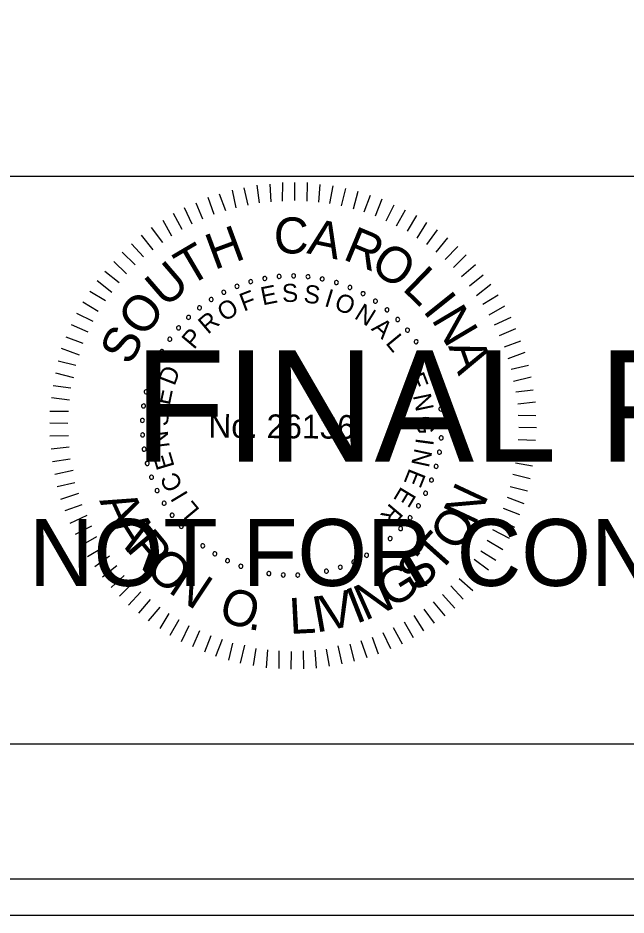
# Model space of a CAD drawing. Extents: x 967 to 1326, y 964 to 1744.
# Drawn here: x 1170.56 to 1189.3, y 963.72 to 991.36 of the extents above; entities that cross this region are included whole.
import ezdxf

# ---------------------------------------------------------------- set-up
doc = ezdxf.new("R2010")
doc.units = 0
for name, color, linetype in [('RD_PD_PaveShd', 7, 'Continuous'), ('RD_XS_Base', 7, 'Continuous'), ('RD_XS_CurbBase', 7, 'Continuous'), ('RD_XS_TieSlope', 7, 'Continuous'), ('RD_XS_TX_TOC', 7, 'Continuous')]:
    doc.layers.add(name, color=color, linetype=linetype)

msp = doc.modelspace()

# ---------------------------------------------------------------- linework, layer by layer
at = {"layer": 'RD_PD_PaveShd'}
for p, q in [((996.114, 986.486), (1323.886, 986.486)), ((1323.886, 968.983), (996.114, 968.983))]:
    msp.add_line(p, q, dxfattribs=at)
at = {"layer": 'RD_XS_CurbBase'}
msp.add_lwpolyline([(967.409, 963.72), (1326.285, 963.72), (1326.285, 1183.72), (967.409, 1183.72)], close=True, dxfattribs=at)
at = {"layer": 'RD_XS_TieSlope'}
for p, q in [((1178.01, 985.663), (1177.93, 986.209)), ((1178.364, 985.699), (1178.33, 986.244)), ((1178.717, 985.719), (1178.722, 986.295)), ((1179.093, 985.739), (1179.098, 986.292)), ((1179.469, 985.713), (1179.489, 986.288)), ((1179.829, 985.687), (1179.872, 986.231)), ((1180.174, 985.646), (1180.271, 986.19)), ((1176.964, 985.419), (1176.769, 985.935)), ((1177.287, 985.508), (1177.169, 986.054)), ((1177.657, 985.597), (1177.53, 986.128)), ((1180.535, 985.573), (1180.662, 986.102)), ((1180.902, 985.478), (1181.045, 986.022)), ((1176.264, 985.156), (1176.053, 985.657)), ((1176.61, 985.306), (1176.423, 985.83)), ((1181.231, 985.384), (1181.428, 985.896)), ((1181.584, 985.265), (1181.78, 985.786)), ((1175.933, 985.005), (1175.699, 985.506)), ((1181.905, 985.109), (1182.154, 985.606)), ((1182.226, 984.953), (1182.506, 985.45)), ((1175.308, 984.634), (1175.036, 985.12)), ((1175.624, 984.846), (1175.352, 985.332)), ((1182.562, 984.789), (1182.85, 985.27)), ((1175.03, 984.445), (1174.681, 984.9)), ((1182.86, 984.572), (1183.163, 985.053)), ((1183.158, 984.378), (1183.484, 984.828)), ((1174.729, 984.217), (1174.372, 984.665)), ((1183.447, 984.145), (1183.811, 984.587)), ((1174.435, 983.997), (1174.062, 984.399)), ((1183.729, 983.92), (1184.116, 984.316)), ((1174.172, 983.753), (1173.776, 984.148)), ((1183.98, 983.672), (1184.368, 984.061)), ((1173.909, 983.479), (1173.52, 983.858)), ((1184.232, 983.394), (1184.657, 983.767)), ((1173.684, 983.197), (1173.242, 983.546)), ((1184.475, 983.108), (1184.892, 983.45)), ((1173.451, 982.9), (1173.009, 983.256)), ((1184.687, 982.807), (1185.128, 983.156)), ((1173.257, 982.64), (1172.776, 982.936)), ((1173.039, 982.312), (1172.559, 982.6)), ((1184.885, 982.544), (1185.355, 982.832)), ((1185.081, 982.213), (1185.56, 982.493)), ((1172.883, 982.006), (1172.379, 982.256)), ((1185.24, 981.904), (1185.756, 982.145)), ((1172.727, 981.677), (1172.215, 981.904)), ((1185.399, 981.573), (1185.907, 981.791)), ((1172.571, 981.333), (1172.051, 981.53)), ((1185.549, 981.226), (1186.057, 981.414)), ((1172.461, 980.974), (1171.91, 981.178)), ((1185.669, 980.865), (1186.185, 981.06)), ((1172.351, 980.652), (1171.807, 980.787)), ((1185.759, 980.541), (1186.297, 980.667)), ((1172.286, 980.276), (1171.727, 980.419)), ((1185.832, 980.165), (1186.371, 980.298)), ((1172.191, 979.955), (1171.647, 980.029)), ((1185.906, 979.842), (1186.436, 979.906)), ((1172.15, 979.587), (1171.598, 979.653)), ((1185.964, 979.473), (1186.51, 979.53)), ((1172.124, 979.234), (1171.548, 979.239)), ((1185.977, 979.12), (1186.514, 979.115)), ((1172.105, 978.866), (1171.545, 978.871)), ((1185.997, 978.751), (1186.542, 978.747)), ((1172.118, 978.482), (1171.542, 978.471)), ((1185.971, 978.368), (1186.508, 978.348)), ((1172.138, 978.136), (1171.585, 978.072)), ((1185.952, 978.022), (1186.497, 977.949)), ((1172.173, 977.768), (1171.627, 977.688)), ((1185.888, 977.655), (1186.417, 977.566)), ((1172.262, 977.414), (1171.701, 977.296)), ((1185.808, 977.302), (1186.345, 977.175)), ((1172.321, 977.037), (1171.774, 976.911)), ((1185.729, 976.926), (1186.265, 976.792)), ((1172.425, 976.707), (1171.871, 976.519)), ((1185.634, 976.597), (1186.146, 976.401)), ((1172.53, 976.36), (1172.007, 976.173)), ((1185.508, 976.253), (1186.013, 976.057)), ((1172.681, 976.029), (1172.165, 975.788)), ((1172.831, 975.705), (1172.323, 975.441)), ((1185.352, 975.924), (1185.857, 975.675)), ((1185.188, 975.603), (1185.7, 975.33)), ((1172.982, 975.374), (1172.497, 975.094)), ((1185.024, 975.274), (1185.498, 974.987)), ((1173.194, 975.042), (1172.709, 974.762)), ((1184.822, 974.946), (1185.288, 974.658)), ((1173.384, 974.78), (1172.936, 974.453)), ((1184.62, 974.687), (1185.055, 974.353)), ((1173.612, 974.478), (1173.164, 974.129)), ((1184.403, 974.389), (1184.814, 974.033)), ((1173.832, 974.177), (1173.437, 973.812)), ((1184.155, 974.092), (1184.574, 973.72)), ((1174.091, 973.945), (1173.689, 973.541)), ((1183.899, 973.864), (1184.28, 973.454)), ((1174.35, 973.674), (1173.97, 973.263)), ((1183.644, 973.597), (1184.024, 973.18)), ((1174.64, 973.442), (1174.275, 973.022)), ((1174.937, 973.209), (1174.58, 972.782)), ((1183.358, 973.37), (1183.715, 972.944)), ((1175.212, 973.014), (1174.932, 972.549)), ((1182.764, 972.952), (1183.059, 972.482)), ((1183.065, 973.141), (1183.384, 972.709)), ((1175.525, 972.812), (1175.245, 972.331)), ((1182.463, 972.755), (1182.743, 972.269)), ((1175.83, 972.633), (1175.588, 972.136)), ((1176.159, 972.477), (1175.94, 971.98)), ((1181.8, 972.431), (1182.041, 971.93)), ((1182.124, 972.581), (1182.396, 972.08)), ((1176.503, 972.321), (1176.307, 971.816)), ((1176.855, 972.211), (1176.651, 971.69)), ((1177.177, 972.1), (1177.05, 971.572)), ((1181.122, 972.175), (1181.31, 971.652)), ((1181.476, 972.28), (1181.664, 971.771)), ((1177.545, 972.036), (1177.409, 971.484)), ((1177.897, 971.933), (1177.808, 971.412)), ((1178.25, 971.892), (1178.207, 971.34)), ((1178.603, 971.866), (1178.598, 971.313)), ((1178.978, 971.84), (1178.974, 971.295)), ((1179.355, 971.86), (1179.365, 971.307)), ((1179.715, 971.88), (1179.749, 971.327)), ((1180.061, 971.915), (1180.149, 971.393)), ((1180.423, 972.012), (1180.541, 971.458)), ((1180.791, 972.07), (1180.926, 971.54))]:
    msp.add_line(p, q, dxfattribs=at)
for centre, start, end in [((1178.609, 983.397), 5.0653, 185.0653), ((1179.055, 983.414), 359.5268, 179.5268), ((1179.5, 983.388), 353.9884, 173.9884), ((1177.312, 983.091), 21.6807, 201.6807), ((1177.734, 983.235), 16.1422, 196.1422), ((1177.734, 983.235), 196.1422, 16.1422), ((1178.168, 983.337), 10.6038, 190.6038), ((1178.168, 983.337), 190.6038, 10.6038), ((1178.609, 983.397), 185.0653, 5.0653), ((1179.055, 983.414), 179.5268, 359.5268), ((1179.5, 983.388), 173.9884, 353.9884), ((1179.94, 983.319), 168.4499, 348.4499), ((1179.94, 983.319), 348.4499, 168.4499), ((1180.372, 983.208), 162.9114, 342.9114), ((1180.372, 983.208), 342.9114, 162.9114), ((1176.906, 982.908), 27.2191, 207.2191), ((1176.906, 982.908), 207.2191, 27.2191), ((1177.312, 983.091), 201.6807, 21.6807), ((1180.79, 983.056), 157.373, 337.373), ((1180.79, 983.056), 337.373, 157.373), ((1181.193, 982.864), 151.8345, 331.8345), ((1181.193, 982.864), 331.8345, 151.8345), ((1176.52, 982.686), 32.7576, 212.7576), ((1176.52, 982.686), 212.7576, 32.7576), ((1181.574, 982.634), 146.2961, 326.2961), ((1181.574, 982.634), 326.2961, 146.2961), ((1176.156, 982.428), 38.2961, 218.2961), ((1176.156, 982.428), 218.2961, 38.2961), ((1181.932, 982.368), 140.7576, 320.7576), ((1181.932, 982.368), 320.7576, 140.7576), ((1175.82, 982.135), 43.8345, 223.8345), ((1175.82, 982.135), 223.8345, 43.8345), ((1182.263, 982.069), 135.2191, 315.2191), ((1182.263, 982.069), 315.2191, 135.2191), ((1175.513, 981.812), 49.373, 229.373), ((1175.513, 981.812), 229.373, 49.373), ((1182.563, 981.74), 129.6807, 309.6807), ((1182.563, 981.74), 309.6807, 129.6807), ((1175.239, 981.461), 54.9114, 234.9114), ((1175.239, 981.461), 234.9114, 54.9114), ((1182.83, 981.383), 124.1422, 304.1422), ((1182.83, 981.383), 304.1422, 124.1422), ((1175, 981.085), 60.4499, 240.4499), ((1175, 981.085), 240.4499, 60.4499), ((1183.061, 981.002), 118.6038, 298.6038), ((1183.061, 981.002), 298.6038, 118.6038), ((1174.798, 980.687), 65.9884, 245.9884), ((1174.798, 980.687), 245.9884, 65.9884), ((1183.255, 980.601), 293.0653, 113.0653), ((1183.255, 980.601), 113.0653, 293.0653), ((1174.636, 980.272), 71.5268, 251.5268), ((1174.636, 980.272), 251.5268, 71.5268), ((1183.408, 980.182), 107.5268, 287.5268), ((1183.408, 980.182), 287.5268, 107.5268), ((1174.514, 979.843), 77.0653, 257.0653), ((1174.514, 979.843), 257.0653, 77.0653), ((1183.521, 979.751), 101.9884, 281.9884), ((1183.521, 979.751), 281.9884, 101.9884), ((1174.435, 979.405), 82.6038, 262.6038), ((1174.435, 979.405), 262.6038, 82.6038), ((1183.592, 979.311), 96.4499, 276.4499), ((1183.592, 979.311), 276.4499, 96.4499), ((1174.398, 978.961), 88.1422, 268.1422), ((1174.398, 978.961), 268.1422, 88.1422), ((1183.619, 978.866), 90.9114, 270.9114), ((1183.619, 978.866), 270.9114, 90.9114), ((1174.404, 978.515), 93.6807, 273.6807), ((1174.404, 978.515), 273.6807, 93.6807), ((1183.604, 978.421), 85.373, 265.373), ((1183.604, 978.421), 265.373, 85.373), ((1174.453, 978.072), 99.2191, 279.2191), ((1174.453, 978.072), 279.2191, 99.2191), ((1183.546, 977.979), 79.8345, 259.8345), ((1183.546, 977.979), 259.8345, 79.8345), ((1174.545, 977.636), 104.7576, 284.7576), ((1174.545, 977.636), 284.7576, 104.7576), ((1183.445, 977.545), 74.2961, 254.2961), ((1183.445, 977.545), 254.2961, 74.2961), ((1174.678, 977.211), 110.2961, 290.2961), ((1174.678, 977.211), 290.2961, 110.2961), ((1183.303, 977.122), 68.7576, 248.7576), ((1183.303, 977.122), 248.7576, 68.7576), ((1174.852, 976.8), 115.8345, 295.8345), ((1174.852, 976.8), 295.8345, 115.8345), ((1183.121, 976.716), 63.2191, 243.2191), ((1183.121, 976.716), 243.2191, 63.2191), ((1175.065, 976.409), 121.373, 301.373), ((1175.065, 976.409), 301.373, 121.373), ((1182.9, 976.328), 57.6807, 237.6807), ((1182.9, 976.328), 237.6807, 57.6807), ((1175.314, 976.039), 126.9114, 306.9114), ((1175.314, 976.039), 306.9114, 126.9114), ((1182.643, 975.964), 52.1422, 232.1422), ((1182.643, 975.964), 232.1422, 52.1422), ((1175.598, 975.696), 132.4499, 312.4499), ((1175.598, 975.696), 312.4499, 132.4499), ((1182.353, 975.627), 46.6038, 226.6038), ((1175.914, 975.381), 137.9884, 317.9884), ((1175.914, 975.381), 317.9884, 137.9884), ((1182.353, 975.627), 226.6038, 46.6038), ((1176.258, 975.099), 143.5268, 323.5268), ((1176.258, 975.099), 323.5268, 143.5268), ((1182.03, 975.319), 41.0653, 221.0653), ((1182.03, 975.319), 221.0653, 41.0653), ((1176.629, 974.851), 149.0653, 329.0653), ((1176.629, 974.851), 329.0653, 149.0653), ((1181.305, 974.803), 29.9884, 209.9884), ((1181.68, 975.043), 35.5268, 215.5268), ((1181.68, 975.043), 215.5268, 35.5268), ((1177.021, 974.639), 154.6038, 334.6038), ((1177.021, 974.639), 334.6038, 154.6038), ((1180.908, 974.6), 24.4499, 204.4499), ((1180.908, 974.6), 204.4499, 24.4499), ((1181.305, 974.803), 209.9884, 29.9884), ((1177.432, 974.467), 160.1422, 340.1422), ((1177.432, 974.467), 340.1422, 160.1422), ((1177.858, 974.335), 165.6807, 345.6807), ((1177.858, 974.335), 345.6807, 165.6807), ((1178.294, 974.245), 351.2191, 171.2191), ((1180.065, 974.313), 13.373, 193.373), ((1180.065, 974.313), 193.373, 13.373), ((1180.494, 974.436), 18.9114, 198.9114), ((1180.494, 974.436), 198.9114, 18.9114), ((1178.294, 974.245), 171.2191, 351.2191), ((1178.737, 974.198), 356.7576, 176.7576), ((1178.737, 974.198), 176.7576, 356.7576), ((1179.183, 974.193), 2.2961, 182.2961), ((1179.183, 974.193), 182.2961, 2.2961), ((1179.627, 974.232), 7.8345, 187.8345), ((1179.627, 974.232), 187.8345, 7.8345)]:
    msp.add_arc(centre, 0.0627, start, end, dxfattribs=at)
at = {"layer": 'RD_XS_TX_TOC'}
for points in [[(967.409, 963.72), (1326.285, 963.72), (1326.285, 1183.72), (967.409, 1183.72)], [(988.525, 964.84), (1326.285, 964.84), (1326.285, 1182.6), (988.525, 1182.6)]]:
    msp.add_lwpolyline(points, close=True, dxfattribs=at)

# ---------------------------------------------------------------- texts
at = {"layer": 'RD_XS_Base'}
for s, height, p in [('FINAL PLANS', 3.4375, (1174.145, 977.685)), ('NOT FOR CONSTRUCTION', 2.0625, (1170.901, 973.86))]:
    msp.add_text(s, height=height, dxfattribs=at).set_placement(p)
at = {"layer": 'RD_XS_TieSlope'}
for s, height, rotation, p in [('C', 1.11, 359.5482, (1178.442, 984.108)), ('A', 1.11, 348.1981, (1179.439, 984.115)), ('H', 1.11, 20.3637, (1176.614, 983.587)), ('R', 1.11, 337.4344, (1180.541, 983.937)), ('T', 1.11, 30.4992, (1175.828, 983.072)), ('O', 1.108, 326.5869, (1181.366, 983.609)), ('U', 1.11, 40.8022, (1175.102, 982.403)), ('L', 1.11, 315.9488, (1182.373, 983.003)), ('S', 0.557, 2.208, (1178.709, 982.601)), ('F', 0.557, 20.6127, (1177.52, 982.309)), ('E', 0.557, 11.4103, (1178.103, 982.503)), ('S', 0.557, 352.6608, (1179.346, 982.599)), ('I', 0.557, 343.1136, (1179.975, 982.491)), ('I', 1.11, 308.6613, (1183.011, 982.338)), ('O', 1.11, 52.0267, (1174.435, 981.474)), ('O', 0.557, 30.8477, (1176.917, 981.987)), ('O', 0.557, 338.4392, (1180.274, 982.401)), ('N', 0.557, 328.2042, (1180.896, 982.12)), ('N', 1.11, 300.7037, (1183.285, 982.075)), ('R', 0.557, 40.3949, (1176.415, 981.594)), ('A', 0.557, 318.657, (1181.424, 981.762)), ('S', 1.108, 63.2511, (1174.029, 980.619)), ('P', 0.557, 49.9421, (1175.985, 981.124)), ('L', 0.557, 309.4546, (1181.869, 981.339)), ('A', 1.11, 289.4792, (1183.814, 981.243)), ('D', 0.557, 69.0364, (1175.386, 980.003)), ('E', 0.557, 291.049, (1182.53, 980.307)), ('E', 0.557, 78.2388, (1175.238, 979.407)), ('N', 0.557, 281.8466, (1182.728, 979.726)), ('S', 0.557, 87.786, (1175.187, 978.772)), ('No. 26136', 0.7311, 359.5268, (1176.429, 978.43)), ('G', 0.557, 272.2995, (1182.833, 979.097)), ('N', 0.557, 97.3332, (1175.242, 978.137)), ('I', 0.557, 262.4084, (1182.83, 978.437)), ('E', 0.557, 106.5355, (1175.394, 977.541)), ('N', 0.557, 257.7339, (1182.789, 978.127)), ('E', 0.557, 248.1867, (1182.628, 977.511)), ('C', 0.557, 116.4266, (1175.661, 976.938)), ('E', 0.557, 238.9844, (1182.378, 976.949)), ('N', 1.105, 64.8922, (1184.632, 975.684)), ('A', 1.105, 294.7297, (1173.062, 976.486)), ('I', 0.557, 121.1011, (1175.823, 976.67)), ('L', 0.557, 129.9595, (1176.187, 976.204)), ('R', 0.557, 229.782, (1182.041, 976.435)), ('O', 1.105, 56.2059, (1184.102, 974.874)), ('A', 1.105, 302.2892, (1173.414, 975.72)), ('R', 1.105, 309.8487, (1173.865, 975.007)), ('T', 1.105, 48.2685, (1183.515, 974.211)), ('O', 1.105, 317.7861, (1174.434, 974.33)), ('S', 1.105, 40.3311, (1182.842, 973.636)), ('N', 1.105, 326.4725, (1175.158, 973.686)), ('G', 1.105, 32.0198, (1182.059, 973.14)), ('N', 1.105, 24.0824, (1181.252, 972.776)), ('O', 1.105, 342.3472, (1176.697, 972.82)), ('V', 1.105, 12.7741, (1180.033, 972.457)), ('I', 1.105, 21.4605, (1180.976, 972.681)), ('L', 1.105, 2.9677, (1178.943, 972.379)), ('I', 1.105, 10.1523, (1179.743, 972.418)), ('.', 1.105, 351.0336, (1177.623, 972.536))]:
    msp.add_text(s, height=height, rotation=rotation, dxfattribs=at).set_placement(p)

doc.saveas('drawing.dxf')
